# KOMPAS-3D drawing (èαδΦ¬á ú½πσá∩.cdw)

Views: Вид 1
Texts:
  Крышка
  Андрей
  Noncommercial version
  Ra3.2
  Ra6.3
  Ra12,5
  Уклоны формовочные по ГОСТ 3212-80.
  Необработанные внутренние поверхности покрыть грунтовкой.
  СЧ15 ГОСТ 1412-85
  ТФ ДГТУ
  ОКМА-30.06.01.00.15-
Dimensions and other numbers on the sheet: 110; 150; 100; 38; 22; 1,5; 20; 0,02; 180; 6 отв.; 10; 0,8; 4; 1:2; 1; 0,45; 0; 2; 3; 5; 6; 7; 8; 9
